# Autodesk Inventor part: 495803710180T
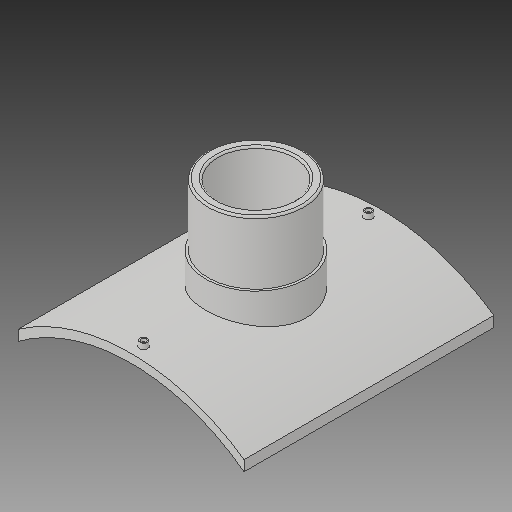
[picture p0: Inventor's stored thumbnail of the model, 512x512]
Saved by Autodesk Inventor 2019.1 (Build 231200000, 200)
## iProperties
Created: 2017-10
Part Number: 495803710180T
Material: Generic
Description: PLASSON BRANCH SADDLE  710x180
Document SubType Name: Modeling
Designer: KIM
Mass: 2754.05 g
Surface Area: 3037.44 cm^2
Volume: 2754.05 cm^3
Density: 1 g/cm^3
Appearance: Default
Author: KIM
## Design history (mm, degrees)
derived "495803.ipt"
feature "Solid1::495803.ipt"
tag "TaggingFeature1"
body "Solid1"
other parameters: "d1" = 16, "d2" = 425, "d4" = 0, "d12" = 380.6, "d13" = 14, "d14" = 211.5, "d16" = 5 deg, "d18" = 4, "d19" = 14, "d20" = 0, "d21" = 3, "d22" = 0, "d24" = 189, "d25" = 16, "d26" = 144, "d28" = 0, "d29" = 9.6, "d31" = 0, "d32" = 84.5, "d33" = 0, "d34" = 7.1, "d37" = 118.3, "d38" = 0, "d39" = 3.55, "B_" = 425, "H_" = 169, "x_" = 16, "D_" = 16
